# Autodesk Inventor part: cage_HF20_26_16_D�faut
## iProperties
Created: 2011-01
Part Number: cage_HF20_26_16_D�faut
Document SubType Name: Modeling
Designer: eric
Density: 1 g/cm^3
Mass: 1.73301 g
Surface Area: 30.9074 cm^2
Volume: 1.73301 cm^3
Author: eric
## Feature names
1. Base1
